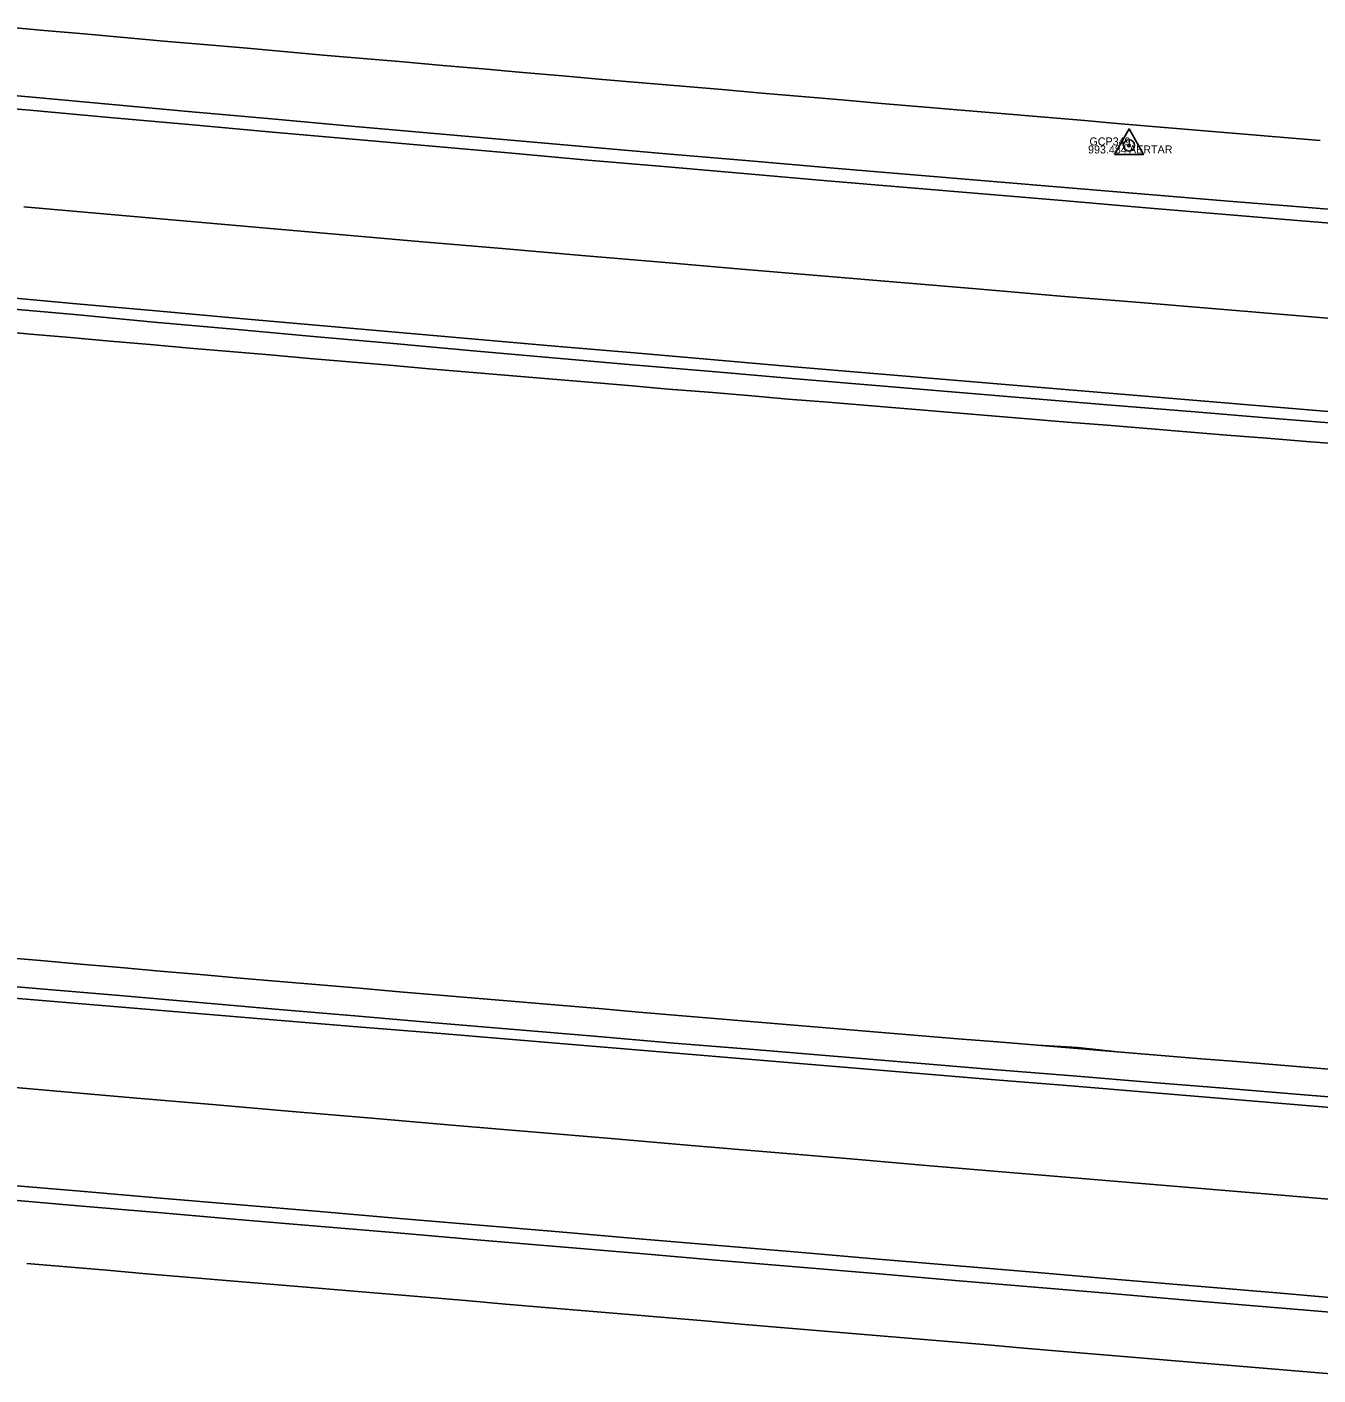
# Model space of a CAD drawing. Extents: x 2065431 to 2068157, y 709104 to 709719.
# Drawn here: x 2067673.1 to 2067834.4, y 709240.4 to 709408.8 of the extents above; entities that cross this region are included whole.
import ezdxf

# ---------------------------------------------------------------- set-up
doc = ezdxf.new("R2010")
doc.units = 0
for name, color, linetype in [('DT_X_Terrain_Boundary', 7, 'Continuous'), ('PM_X_Edge_Line', 7, 'Continuous'), ('PM_X_Lane_Line', 7, 'Continuous'), ('PV_X_EOP', 7, 'Continuous'), ('PV_X_Shoulder_Rumble_Strip', 7, 'Continuous'), ('SV_P_Aerial_Targets', 7, 'Continuous'), ('SV_X_Mon_Cells_Found', 7, 'Continuous'), ('SV_X_Text_Elevation', 7, 'Continuous'), ('SV_X_Text_Name', 7, 'Continuous')]:
    doc.layers.add(name, color=color, linetype=linetype)

msp = doc.modelspace()

# ---------------------------------------------------------------- linework, layer by layer
at = {"layer": 'DT_X_Terrain_Boundary'}
for points in [[(2067834.67, 709394.64), (2067829.68, 709395.06), (2067824.7, 709395.48), (2067819.72, 709395.9), (2067814.74, 709396.32), (2067809.75, 709396.74), (2067804.77, 709397.16), (2067799.79, 709397.58), (2067794.81, 709398.01), (2067789.83, 709398.43), (2067784.84, 709398.85), (2067779.86, 709399.28), (2067774.88, 709399.71), (2067769.9, 709400.13), (2067764.92, 709400.56), (2067759.94, 709400.99), (2067754.95, 709401.42), (2067749.97, 709401.85), (2067744.99, 709402.28), (2067740.01, 709402.71), (2067735.03, 709403.15), (2067730.05, 709403.58), (2067725.07, 709404.01), (2067720.09, 709404.45), (2067715.1, 709404.88), (2067710.12, 709405.32), (2067705.14, 709405.76), (2067700.16, 709406.2), (2067695.18, 709406.63), (2067690.2, 709407.07), (2067685.22, 709407.51), (2067680.24, 709407.96), (2067675.26, 709408.39), (2067670.28, 709408.82)], [(2067668.56, 709370.89), (2067673.54, 709370.46), (2067678.52, 709370.02), (2067683.5, 709369.58), (2067688.48, 709369.15), (2067693.46, 709368.71), (2067698.44, 709368.28), (2067703.42, 709367.85), (2067708.41, 709367.42), (2067713.39, 709366.99), (2067718.37, 709366.56), (2067723.35, 709366.13), (2067728.33, 709365.71), (2067733.31, 709365.28), (2067738.3, 709364.86), (2067743.28, 709364.44), (2067748.26, 709364.01), (2067753.24, 709363.59), (2067758.23, 709363.18), (2067763.21, 709362.76), (2067768.19, 709362.34), (2067773.17, 709361.93), (2067778.16, 709361.51), (2067783.14, 709361.1), (2067788.12, 709360.69), (2067793.11, 709360.28), (2067798.09, 709359.87), (2067803.07, 709359.46), (2067808.06, 709359.06), (2067813.04, 709358.65), (2067818.02, 709358.25), (2067823.01, 709357.84), (2067827.99, 709357.44), (2067832.97, 709357.04), (2067837.96, 709356.64)], [(2067839.22, 709278.34), (2067834.24, 709278.75), (2067829.25, 709279.15), (2067824.27, 709279.56), (2067819.29, 709279.96), (2067814.3, 709280.37), (2067809.32, 709280.78), (2067804.35, 709281.32), (2067799.35, 709281.6), (2067794.37, 709282.01), (2067789.39, 709282.42), (2067784.4, 709282.83), (2067779.42, 709283.25), (2067774.44, 709283.66), (2067769.46, 709284.08), (2067764.47, 709284.49), (2067759.49, 709284.91), (2067754.51, 709285.33), (2067749.53, 709285.75), (2067744.54, 709286.17), (2067739.56, 709286.59), (2067734.58, 709287.02), (2067729.6, 709287.44), (2067724.62, 709287.87), (2067719.63, 709288.29), (2067714.65, 709288.72), (2067709.67, 709289.15), (2067704.69, 709289.57), (2067699.71, 709290), (2067694.73, 709290.43), (2067689.74, 709290.87), (2067684.76, 709291.3), (2067679.78, 709291.73), (2067674.8, 709292.17), (2067669.82, 709292.6)], [(2067673.09, 709254.33), (2067678.07, 709253.91), (2067683.05, 709253.49), (2067688.03, 709253.06), (2067693.02, 709252.64), (2067698, 709252.22), (2067702.98, 709251.8), (2067707.96, 709251.38), (2067712.94, 709250.95), (2067717.93, 709250.53), (2067722.91, 709250.11), (2067727.89, 709249.69), (2067732.87, 709249.26), (2067737.85, 709248.84), (2067742.84, 709248.42), (2067747.82, 709248), (2067752.8, 709247.57), (2067757.78, 709247.15), (2067762.77, 709246.73), (2067767.75, 709246.31), (2067772.73, 709245.89), (2067777.71, 709245.46), (2067782.69, 709245.04), (2067787.68, 709244.62), (2067792.66, 709244.2), (2067797.64, 709243.77), (2067802.62, 709243.35), (2067807.6, 709242.93), (2067812.59, 709242.51), (2067817.57, 709242.08), (2067822.55, 709241.66), (2067827.53, 709241.24), (2067832.52, 709240.82), (2067837.5, 709240.4)]]:
    msp.add_lwpolyline(points, dxfattribs=at)
at = {"layer": 'PM_X_Edge_Line'}
for points in [[(2067663.48, 709399.28), (2067673.45, 709398.41), (2067683.41, 709397.52), (2067693.37, 709396.62), (2067703.33, 709395.73), (2067713.29, 709394.84), (2067723.25, 709393.96), (2067733.21, 709393.08), (2067743.17, 709392.2), (2067753.13, 709391.34), (2067763.1, 709390.47), (2067773.06, 709389.62), (2067783.02, 709388.76), (2067792.99, 709387.92), (2067802.95, 709387.08), (2067812.92, 709386.24), (2067822.88, 709385.41), (2067832.85, 709384.58), (2067842.81, 709383.76)], [(2067669.33, 709375.15), (2067679.29, 709374.24), (2067689.25, 709373.35), (2067699.21, 709372.46), (2067709.17, 709371.58), (2067719.13, 709370.7), (2067729.09, 709369.83), (2067739.05, 709368.96), (2067749.01, 709368.09), (2067758.98, 709367.24), (2067768.94, 709366.38), (2067778.9, 709365.53), (2067788.87, 709364.69), (2067798.83, 709363.85), (2067808.8, 709363.01), (2067818.76, 709362.18), (2067828.73, 709361.35), (2067838.7, 709360.53)], [(2067664.01, 709288.11), (2067673.97, 709287.26), (2067683.94, 709286.44), (2067693.9, 709285.61), (2067703.87, 709284.78), (2067713.83, 709283.95), (2067723.8, 709283.13), (2067733.76, 709282.3), (2067743.73, 709281.47), (2067753.7, 709280.64), (2067763.66, 709279.82), (2067773.63, 709278.99), (2067783.59, 709278.16), (2067793.56, 709277.33), (2067803.52, 709276.51), (2067813.49, 709275.68), (2067823.46, 709274.85), (2067833.42, 709274.02), (2067843.39, 709273.2)], [(2067669.83, 709264.2), (2067679.8, 709263.35), (2067689.76, 709262.5), (2067699.72, 709261.66), (2067709.69, 709260.81), (2067719.65, 709259.96), (2067729.62, 709259.12), (2067739.58, 709258.27), (2067749.54, 709257.42), (2067759.51, 709256.58), (2067769.47, 709255.73), (2067779.44, 709254.88), (2067789.4, 709254.03), (2067799.36, 709253.19), (2067809.33, 709252.34), (2067819.29, 709251.49), (2067829.26, 709250.65), (2067839.22, 709249.8)]]:
    msp.add_lwpolyline(points, dxfattribs=at)
at = {"layer": 'PM_X_Lane_Line'}
for points in [[(2067672.69, 709386.36), (2067682.66, 709385.47), (2067692.62, 709384.6), (2067702.58, 709383.73), (2067712.54, 709382.86), (2067722.5, 709381.99), (2067732.47, 709381.13), (2067742.43, 709380.28), (2067752.39, 709379.42), (2067762.36, 709378.57), (2067772.32, 709377.73), (2067782.29, 709376.88), (2067792.25, 709376.05), (2067802.22, 709375.21), (2067812.18, 709374.38), (2067822.15, 709373.55), (2067832.11, 709372.73), (2067842.08, 709371.91)], [(2067666.39, 709276.76), (2067676.35, 709275.9), (2067686.31, 709275.05), (2067696.27, 709274.19), (2067706.24, 709273.33), (2067716.2, 709272.48), (2067726.17, 709271.63), (2067736.13, 709270.77), (2067746.09, 709269.93), (2067756.06, 709269.08), (2067766.02, 709268.23), (2067775.99, 709267.39), (2067785.95, 709266.55), (2067795.91, 709265.71), (2067805.88, 709264.87), (2067815.84, 709264.03), (2067825.81, 709263.2), (2067835.77, 709262.36)]]:
    msp.add_lwpolyline(points, dxfattribs=at)
at = {"layer": 'PV_X_EOP'}
for points in [[(2067670.28, 709408.82), (2067675.26, 709408.39), (2067680.24, 709407.96), (2067685.22, 709407.51), (2067690.2, 709407.07), (2067695.18, 709406.63), (2067700.16, 709406.2), (2067705.14, 709405.76), (2067710.12, 709405.32), (2067715.1, 709404.88), (2067720.09, 709404.45), (2067725.07, 709404.01), (2067730.05, 709403.58), (2067735.03, 709403.15), (2067740.01, 709402.71), (2067744.99, 709402.28), (2067749.97, 709401.85), (2067754.95, 709401.42), (2067759.94, 709400.99), (2067764.92, 709400.56), (2067769.9, 709400.13), (2067774.88, 709399.71), (2067779.86, 709399.28), (2067784.84, 709398.85), (2067789.83, 709398.43), (2067794.81, 709398.01), (2067799.79, 709397.58), (2067804.77, 709397.16), (2067809.75, 709396.74), (2067814.74, 709396.32), (2067819.72, 709395.9), (2067824.7, 709395.48), (2067829.68, 709395.06), (2067834.67, 709394.64)], [(2067668.56, 709370.89), (2067673.54, 709370.46), (2067678.52, 709370.02), (2067683.5, 709369.58), (2067688.48, 709369.15), (2067693.46, 709368.71), (2067698.44, 709368.28), (2067703.42, 709367.85), (2067708.41, 709367.42), (2067713.39, 709366.99), (2067718.37, 709366.56), (2067723.35, 709366.13), (2067728.33, 709365.71), (2067733.31, 709365.28), (2067738.3, 709364.86), (2067743.28, 709364.44), (2067748.26, 709364.01), (2067753.24, 709363.59), (2067758.23, 709363.18), (2067763.21, 709362.76), (2067768.19, 709362.34), (2067773.17, 709361.93), (2067778.16, 709361.51), (2067783.14, 709361.1), (2067788.12, 709360.69), (2067793.11, 709360.28), (2067798.09, 709359.87), (2067803.07, 709359.46), (2067808.06, 709359.06), (2067813.04, 709358.65), (2067818.02, 709358.25), (2067823.01, 709357.84), (2067827.99, 709357.44), (2067832.97, 709357.04), (2067837.96, 709356.64)], [(2067669.82, 709292.6), (2067674.8, 709292.17), (2067679.78, 709291.73), (2067684.76, 709291.3), (2067689.74, 709290.87), (2067694.73, 709290.43), (2067699.71, 709290), (2067704.69, 709289.57), (2067709.67, 709289.15), (2067714.65, 709288.72), (2067719.63, 709288.29), (2067724.62, 709287.87), (2067729.6, 709287.44), (2067734.58, 709287.02), (2067739.56, 709286.59), (2067744.54, 709286.17), (2067749.53, 709285.75), (2067754.51, 709285.33), (2067759.49, 709284.91), (2067764.47, 709284.49), (2067769.46, 709284.08), (2067774.44, 709283.66), (2067779.42, 709283.25), (2067784.4, 709282.83), (2067789.39, 709282.42), (2067794.37, 709282.01), (2067799.35, 709281.6), (2067804.34, 709281.19), (2067809.32, 709280.78), (2067814.3, 709280.37), (2067819.29, 709279.96), (2067824.27, 709279.56), (2067829.25, 709279.15), (2067834.24, 709278.75), (2067839.22, 709278.34)], [(2067673.09, 709254.33), (2067678.07, 709253.91), (2067683.05, 709253.49), (2067688.03, 709253.06), (2067693.02, 709252.64), (2067698, 709252.22), (2067702.98, 709251.8), (2067707.96, 709251.38), (2067712.94, 709250.95), (2067717.93, 709250.53), (2067722.91, 709250.11), (2067727.89, 709249.69), (2067732.87, 709249.26), (2067737.85, 709248.84), (2067742.84, 709248.42), (2067747.82, 709248), (2067752.8, 709247.57), (2067757.78, 709247.15), (2067762.77, 709246.73), (2067767.75, 709246.31), (2067772.73, 709245.89), (2067777.71, 709245.46), (2067782.69, 709245.04), (2067787.68, 709244.62), (2067792.66, 709244.2), (2067797.64, 709243.77), (2067802.62, 709243.35), (2067807.6, 709242.93), (2067812.59, 709242.51), (2067817.57, 709242.08), (2067822.55, 709241.66), (2067827.53, 709241.24), (2067832.52, 709240.82), (2067837.5, 709240.4)]]:
    msp.add_lwpolyline(points, dxfattribs=at)
at = {"layer": 'PV_X_Shoulder_Rumble_Strip'}
for points in [[(2067663.82, 709400.93), (2067673.78, 709400.04), (2067683.74, 709399.14), (2067693.69, 709398.24), (2067703.65, 709397.34), (2067713.61, 709396.45), (2067723.57, 709395.56), (2067733.54, 709394.69), (2067743.5, 709393.81), (2067753.46, 709392.95), (2067763.42, 709392.09), (2067773.39, 709391.24), (2067783.35, 709390.39), (2067793.32, 709389.55), (2067803.28, 709388.72), (2067813.25, 709387.89), (2067823.21, 709387.07), (2067833.18, 709386.26), (2067843.15, 709385.45)], [(2067669.08, 709373.78), (2067679.03, 709372.88), (2067688.99, 709371.96), (2067698.95, 709371.06), (2067708.91, 709370.16), (2067718.87, 709369.26), (2067728.83, 709368.38), (2067738.79, 709367.5), (2067748.76, 709366.63), (2067758.72, 709365.77), (2067768.68, 709364.92), (2067778.65, 709364.07), (2067788.61, 709363.23), (2067798.58, 709362.4), (2067808.54, 709361.57), (2067818.51, 709360.76), (2067828.48, 709359.95), (2067838.44, 709359.14)], [(2067664.26, 709289.57), (2067674.22, 709288.71), (2067684.18, 709287.84), (2067694.15, 709286.97), (2067704.11, 709286.11), (2067714.07, 709285.26), (2067724.04, 709284.41), (2067734, 709283.56), (2067743.97, 709282.72), (2067753.93, 709281.88), (2067763.9, 709281.05), (2067773.86, 709280.22), (2067783.83, 709279.4), (2067793.79, 709278.58), (2067803.76, 709277.76), (2067813.73, 709276.95), (2067823.69, 709276.15), (2067833.66, 709275.34), (2067843.63, 709274.55)], [(2067669.51, 709262.39), (2067679.47, 709261.54), (2067689.44, 709260.69), (2067699.4, 709259.84), (2067709.36, 709259), (2067719.33, 709258.15), (2067729.29, 709257.3), (2067739.26, 709256.46), (2067749.22, 709255.61), (2067759.18, 709254.76), (2067769.15, 709253.92), (2067779.11, 709253.07), (2067789.08, 709252.22), (2067799.04, 709251.37), (2067809, 709250.53), (2067818.97, 709249.68), (2067828.93, 709248.83), (2067838.9, 709247.99)]]:
    msp.add_lwpolyline(points, dxfattribs=at)
at = {"layer": 'SV_P_Aerial_Targets'}
msp.add_lwpolyline([(2067808.99, 709392.87), (2067812.59, 709392.87), (2067810.79, 709396.09)], close=True, dxfattribs=at)
for radius in [0.7, 0.16]:
    msp.add_circle((2067810.79, 709394.02), radius, dxfattribs=at)

# ---------------------------------------------------------------- texts
at = {"layer": 'SV_X_Mon_Cells_Found'}
msp.add_text('GCP349', height=1, dxfattribs=at).set_placement((2067805.85, 709394.02))
at = {"layer": 'SV_X_Text_Elevation'}
msp.add_text('AERTAR', height=1, dxfattribs=at).set_placement((2067810.79, 709393.02))
at = {"layer": 'SV_X_Text_Name'}
msp.add_text('993.484', height=1, dxfattribs=at).set_placement((2067805.67, 709393.02))

doc.saveas('drawing.dxf')
